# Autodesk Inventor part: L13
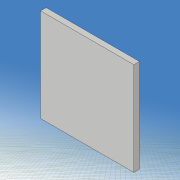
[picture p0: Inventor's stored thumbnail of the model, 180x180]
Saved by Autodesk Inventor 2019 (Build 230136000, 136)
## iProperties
Created: 2021-05
Part Number: L13
Material: 一般
Document SubType Name: Modeling
Designer: kikut
Density: 1 g/cm^3
Appearance: 既定
Mass: 0.00934248 g
Surface Area: 0.426451 cm^2
Volume: 0.00934248 cm^3
Author: kikut
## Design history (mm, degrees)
sketch "スケッチ1"
  geometry: L1 (80, 60)-(-80, 60); L2 (-80, 60)-(-80, -60); L3 (-80, -60)-(80, -60); L4 (80, -60)-(80, 60); L5 (80, 60)-(-80, -60); L6 (-80, 60)-(80, -60); 1 further point
  constraints: 12 end point, 2 midpoint, 2 parallel, 1 horizontal, 1 perpendicular
  dimensions: "d0" = 160 distance of L2.end L3.end; "d1" = 120 distance of L1.end L2.end
extrude "押し出し1" new body sketch "スケッチ1" stored distance "d2" = 0.6; taper "d3" = 0 deg
sketch "スケッチ2"
  geometry: L1 (-140, 0)-(140, 0) reference; L2 (0, -54)-(20, -30); L3 (0, 54)-(20, 30); L4 (0, -3)-(6.514, -3); L5 (6.514, -3)-(16, -6); L6 (16, -6)-(24, -3); L7 (24, -3)-(33.716, -3); L8 (0, 3)-(6.514, 3); L9 (6.514, 3)-(16, 6); L10 (16, 6)-(24, 3); L11 (24, 3)-(33.716, 3); L12 (0, -98)-(0, 98) reference; L13 (-100, -70)-(100, -70); L14 (100, -70)-(100, 70); L15 (100, 70)-(-100, 70); L16 (-100, 70)-(-100, -70); L17 (-100, -70)-(100, 70); L18 (100, -70)-(-100, 70); A1 r 60 centre (54.312, 28.5) between (0, 54) and (0, 3); A2 r 60 centre (54.312, -28.5) between (0, -3) and (0, -54); A3 r 18.111 centre (18, -12) between (20, -30) and (33.716, -3); A4 r 18.111 centre (18, 12) between (33.716, 3) and (20, 30); 1 further point
  constraints: 32 end point, 8 point on circle, 8 symmetric about line, 4 centre point, 3 horizontal, 2 collinear, 2 midpoint, 2 parallel, 1 perpendicular
  dimensions: "d5" = 60 radius of A1; "d6" = 6 distance of L8.start L4.start; "d7" = 108 distance of L3.start L2.start; "d8" = 0 horizontal distance of L3.start L8.start; "d9" = 60 distance of L3.end L2.end; "d10" = 0 horizontal distance of point (0, 0) L3.start; "d11" = 20 horizontal distance of L3.start L3.end; "d12" = 24 distance of A4.centre A3.centre; "d13" = 6 distance of L11.end L7.end; "d14" = 12 distance of L9.end L5.end; "d15" = 16 distance from line of L12 L5.end; "d16" = 24 distance from line of L6.end L12; "d17" = 200 distance of L14.end L15.end; "d18" = 140 distance of L15.end L13.start; "d30" = 18 distance from line of L12 A4.centre
extrude "押し出し2" cut sketch "スケッチ2" stored distance "d19" = 10; taper "d20" = 0 deg
sketch "スケッチ3"
  geometry: L1 (49.705, -17.97)-(33.948, -15.191); L2 (33.948, -15.191)-(34.295, -13.222); L3 (34.295, -13.222)-(50.052, -16); L4 (50.052, -16)-(49.705, -17.97); L5 (49.705, -17.97)-(34.295, -13.222); L6 (33.948, -15.191)-(50.052, -16); L7 (50.052, 16)-(34.295, 13.222); L8 (34.295, 13.222)-(33.948, 15.191); L9 (33.948, 15.191)-(49.705, 17.97); L10 (49.705, 17.97)-(50.052, 16); L11 (50.052, 16)-(33.948, 15.191); L12 (34.295, 13.222)-(49.705, 17.97); L13 (-112, 0)-(112, 0) reference; L14 (0, -84)-(0, 84) reference; 3 further points
  constraints: 24 end point, 4 midpoint, 4 parallel, 2 perpendicular, 2 symmetric about line
  dimensions: "d21" = 2 distance of L3.end L1.start; "d22" = 2 distance of L9.end L7.start; "d23" = 16 distance of L8.end L9.end; "d24" = 42 distance from line of L14 point (42, 15.596); "d26" = 10 deg angle of L7 L13; "d62" = 16 distance from line of L3.end L13
extrude "押し出し3" join sketch "スケッチ3" distance "d27" = 0.6; taper "d28" = 0 deg
fillet "フィレット1" dims "d31" = 2
fillet "フィレット2" dims "d32" = 1
sketch "スケッチ7"
  geometry: L1 (-20, 60)-(80, 60); L2 (80, 60)-(80, -60); L3 (80, -60)-(-20, -60); L4 (-20, -60)-(-20, 60); L5 (0, -82.207)-(0, 85.793) reference; L6 (-40, 0)-(100, 0) reference; L7 (0, -30)-(10, -30); L8 (10, -30)-(10, -40); L9 (10, -40)-(0, -40); L10 (0, -40)-(0, -30); 1 further point
  constraints: 16 end point, 4 parallel, 2 horizontal, 2 perpendicular, 1 other
  dimensions: "d80" = 120 distance of L3.end L1.start; "d81" = 20 distance between parallel lines of L5 L4; "d82" = 100 distance of L1.start L1.end; "d84" = 10 distance of L8.end L9.end; "d85" = 10 distance of L7.end L8.end; "d86" = 20 distance between parallel lines of L4 L10; "d90" = 30 distance between parallel lines of L7 L6
extrude "押し出し5" cut sketch "スケッチ7" stored distance "d87" = 10; taper "d88" = 0 deg
node "ソリッド1"
